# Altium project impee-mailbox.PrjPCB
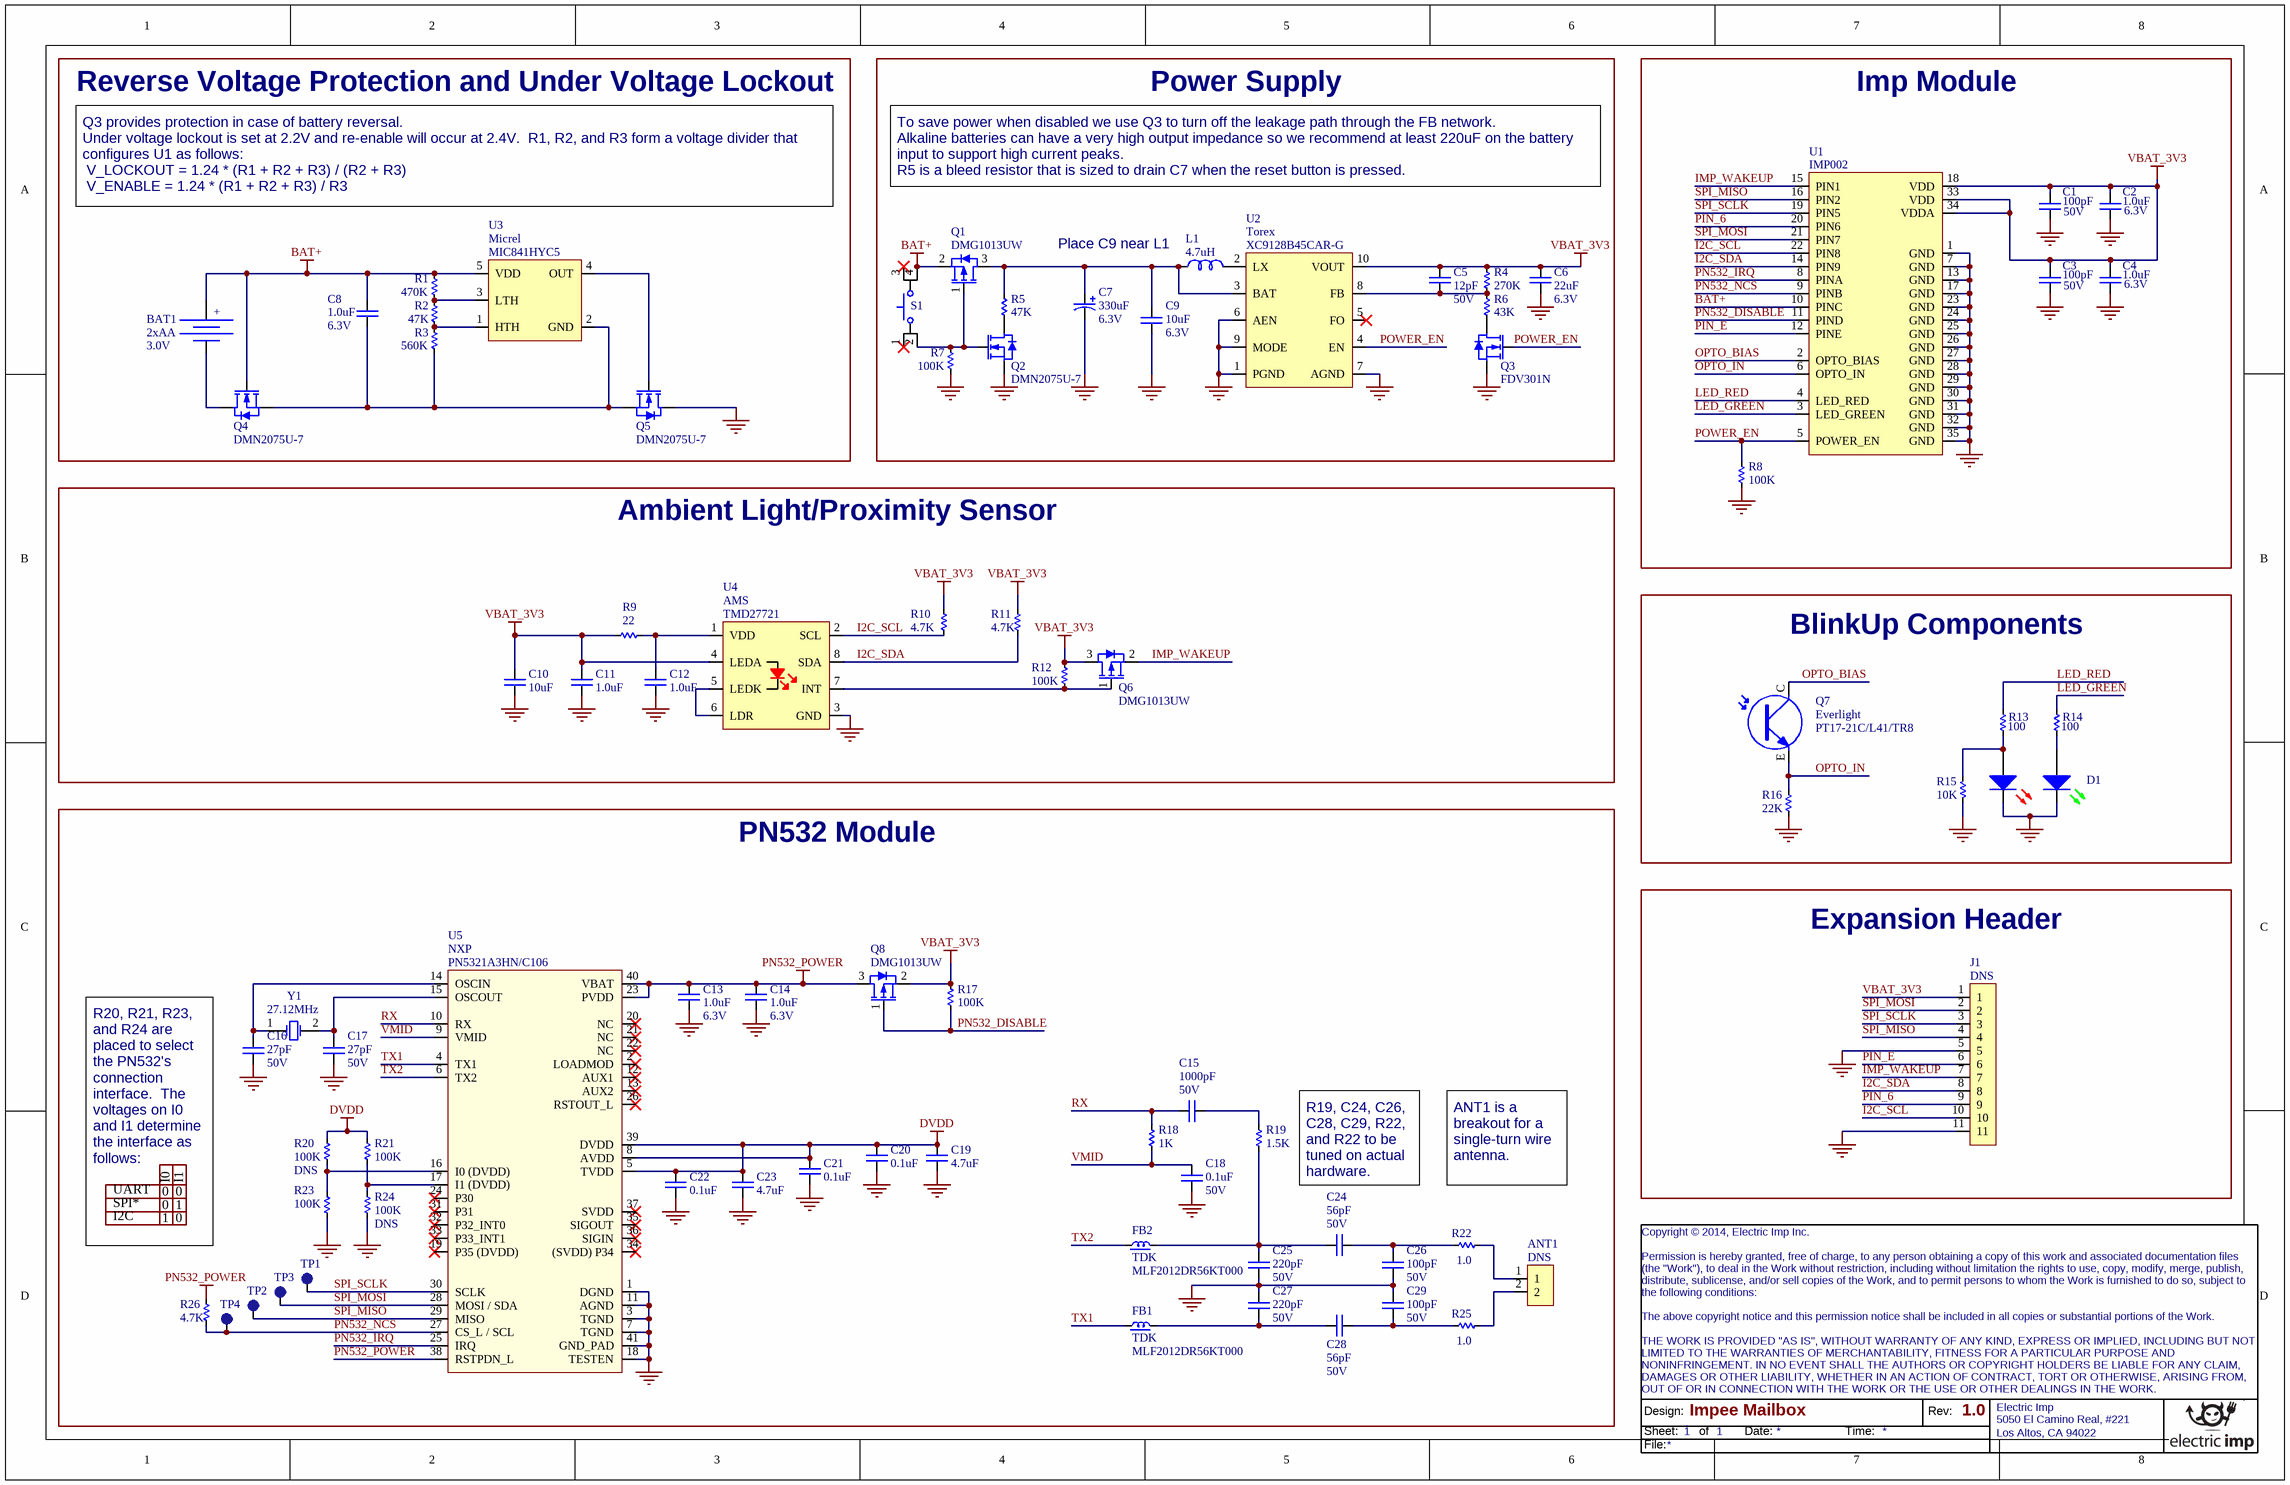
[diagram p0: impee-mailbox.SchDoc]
1 sheet, 81 parts. Net scope: global (net labels, ports and power ports of the same name join across sheets).
Board file: impee-mailbox.PcbDoc

## Sheet impee-mailbox.SchDoc: Impee Mailbox
size Tabloid; Revision: 1.0; SheetNumber: 1; SheetTotal: 1; PageSetup: Record=PageOptions¦CenterHorizontal=True¦CenterVertical=True¦PrintScale=0.90¦XCorrection=1.00¦YCorrection=1.00¦PrintKind=0¦BorderSize=5000000¦LeftOffset=0¦BottomOffset=0¦Orientation=2¦PaperLength=1000¦PaperWidth=1000¦Scale=100¦PaperSource=276¦PrintQuality=-3¦MediaType=1¦DitherType=10¦PrintScaleMode=1¦PaperKind=Tabloid¦PaperIndex=3

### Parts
ANT1  BOMOPTION: DNS  [HDR254P1X2-N]  (hidden comment: Header)  (no BOM)
BAT1  Voltage: 3.0V  Configuration: 2xAA  [12BH321P-GR]  (hidden comment: BATTERY)
C1  value 100pF  Voltage: 50V  [CAPC1005X07N]  (hidden comment: Ceramic Capacitor)
C2  value 1.0uF  Voltage: 6.3V  [CAPC1005X07N]  (hidden comment: Ceramic Capacitor)
C3  value 100pF  Voltage: 50V  [CAPC1005X07N]  (hidden comment: Ceramic Capacitor)
C4  value 1.0uF  Voltage: 6.3V  [CAPC1005X07N]  (hidden comment: Ceramic Capacitor)
C5  value 12pF  Voltage: 50V  [CAPC1005X07N]  (hidden comment: Ceramic Capacitor)
C6  value 22uF  Voltage: 6.3V  [CAPC2012X14N]  (hidden comment: Ceramic Capacitor)
C7  value 330uF  Voltage: 6.3V  [CAPAE8983X55N]  (hidden comment: Polarized Capacitor)
C8  value 1.0uF  Voltage: 6.3V  [CAPC1005X07N]  (hidden comment: Ceramic Capacitor)
C9  value 10uF  Voltage: 6.3V  [CAPC2012X14N]  (hidden comment: Ceramic Capacitor)
C10  value 10uF  [CAPC2012X14N]  (hidden comment: Ceramic Capacitor)
C11  value 1.0uF  [CAPC1005X07N]  (hidden comment: Ceramic Capacitor)
C12  value 1.0uF  [CAPC1005X07N]  (hidden comment: Ceramic Capacitor)
C13  value 1.0uF  Voltage: 6.3V  [CAPC1005X07N]  (hidden comment: Ceramic Capacitor)
C14  value 1.0uF  Voltage: 6.3V  [CAPC1005X07N]  (hidden comment: Ceramic Capacitor)
C15  value 1000pF  Voltage: 50V  [CAPC1005X07N]  (hidden comment: Ceramic Capacitor)
C16  value 27pF  Voltage: 50V  [CAPC1005X07N]  (hidden comment: Ceramic Capacitor)
C17  value 27pF  Voltage: 50V  [CAPC1005X07N]  (hidden comment: Ceramic Capacitor)
C18  value 0.1uF  Voltage: 50V  [CAPC2012X14N]  (hidden comment: Ceramic Capacitor)
C19  value 4.7uF  [CAPC1608X10N]  (hidden comment: Ceramic Capacitor)
C20  value 0.1uF  [CAPC1005X07N]  (hidden comment: Ceramic Capacitor)
C21  value 0.1uF  [CAPC1005X07N]  (hidden comment: Ceramic Capacitor)
C22  value 0.1uF  [CAPC1005X07N]  (hidden comment: Ceramic Capacitor)
C23  value 4.7uF  [CAPC1608X10N]  (hidden comment: Ceramic Capacitor)
C24  value 56pF  Voltage: 50V  [CAPC1005X07N]  (hidden comment: Ceramic Capacitor)
C25  value 220pF  Voltage: 50V  [CAPC1005X07N]  (hidden comment: Ceramic Capacitor)
C26  value 100pF  Voltage: 50V  [CAPC1005X07N]  (hidden comment: Ceramic Capacitor)
C27  value 220pF  Voltage: 50V  [CAPC1005X07N]  (hidden comment: Ceramic Capacitor)
C28  value 56pF  Voltage: 50V  [CAPC1005X07N]  (hidden comment: Ceramic Capacitor)
C29  value 100pF  Voltage: 50V  [CAPC1005X07N]  (hidden comment: Ceramic Capacitor)
D1  LED Red and Green  [LED1616X07N-REDGREEN]  (value not drawn)
FB1  Manufacturer: TDK  Manufacturer Part Number: MLF2012DR56KT000  [INDC2012X11N]  (hidden comment: Ferrite Bead)
FB2  Manufacturer: TDK  Manufacturer Part Number: MLF2012DR56KT000  [INDC2012X11N]  (hidden comment: Ferrite Bead)
J1  BOMOPTION: DNS  [HDR254P1X11-N]  (hidden comment: Header)  (no BOM)
L1  value 4.7uH  [INDP6060X28N]  (hidden comment: Inductor)
Q1  Manufacturer Part Number: DMG1013UW  [SOT65P210X110-3N]  (hidden comment: PFET)
Q2  Manufacturer Part Number: DMN2075U-7  [SOT95P300X130-3N]  (hidden comment: N-Channel MOSFET)
Q3  Manufacturer Part Number: FDV301N  [SOT95P300X130-3N]  (hidden comment: N-Channel MOSFET)
Q4  Manufacturer Part Number: DMN2075U-7  [SOT95P300X130-3N]  (hidden comment: N-Channel MOSFET)
Q5  Manufacturer Part Number: DMN2075U-7  [SOT95P300X130-3N]  (hidden comment: N-Channel MOSFET)
Q6  Manufacturer Part Number: DMG1013UW  [SOT65P210X110-3N]  (hidden comment: PFET)
Q7  Manufacturer: Everlight  Manufacturer Part Number: PT17-21C/L41/TR8  [PHOTOTRANS2012X13]  (hidden comment: PHOTOTRANSISTOR)
Q8  Manufacturer Part Number: DMG1013UW  [SOT65P210X110-3N]  (hidden comment: PFET)
R1  value 470K  [RESC1005X04N]  (hidden comment: Resistor)
R2  value 47K  [RESC1005X04N]  (hidden comment: Resistor)
R3  value 560K  [RESC1005X04N]  (hidden comment: Resistor)
R4  value 270K  [RESC1005X04N]  (hidden comment: Resistor)
R5  value 47K  [RESC1005X04N]  (hidden comment: Resistor)
R6  value 43K  [RESC1005X04N]  (hidden comment: Resistor)
R7  value 100K  [RESC1005X04N]  (hidden comment: Resistor)
R8  value 100K  [RESC1005X04N]  (hidden comment: Resistor)
R9  value 22  [RESC1005X04N]  (hidden comment: Resistor)
R10  value 4.7K  [RESC1005X04N]  (hidden comment: Resistor)
R11  value 4.7K  [RESC1005X04N]  (hidden comment: Resistor)
R12  value 100K  [RESC1005X04N]  (hidden comment: Resistor)
R13  value 100  [RESC1005X04N]  (hidden comment: Resistor)
R14  value 100  [RESC1005X04N]  (hidden comment: Resistor)
R15  value 10K  [RESC1005X04N]  (hidden comment: Resistor)
R16  value 22K  [RESC1005X04N]  (hidden comment: Resistor)
R17  value 100K  [RESC1005X04N]  (hidden comment: Resistor)
R18  value 1K  [RESC1005X04N]  (hidden comment: Resistor)
R19  value 1.5K  [RESC1005X04N]  (hidden comment: Resistor)
R20  value 100K  BOMOPTION: DNS  [RESC1005X04N]  (hidden comment: Resistor)  (no BOM)
R21  value 100K  [RESC1005X04N]  (hidden comment: Resistor)
R22  value 1.0  [RESC2012X07N]  (hidden comment: Resistor)
R23  value 100K  [RESC1005X04N]  (hidden comment: Resistor)
R24  value 100K  BOMOPTION: DNS  [RESC1005X04N]  (hidden comment: Resistor)  (no BOM)
R25  value 1.0  [RESC2012X07N]  (hidden comment: Resistor)
R26  value 4.7K  [RESC1005X04N]  (hidden comment: Resistor)
S1  Push Button  [BTN600X600X430-4N]  (value not drawn)
TP1  Testpoint  [TP254P1X1-TH]  (value not drawn)  (no BOM)
TP2  Testpoint  [TP254P1X1-TH]  (value not drawn)  (no BOM)
TP3  Testpoint  [TP254P1X1-TH]  (value not drawn)  (no BOM)
TP4  Testpoint  [TP254P1X1-TH]  (value not drawn)  (no BOM)
U1  Manufacturer Part Number: IMP002  [IMP_MODULE]  (hidden comment: imp module)
U2  Manufacturer: Torex  Manufacturer Part Number: XC9128B45CAR-G  [MSOP50P490X116-10N]  (hidden comment: XC9128)
U3  Manufacturer: Micrel  Manufacturer Part Number: MIC841HYC5  [SOT65P200X125-5N]  (hidden comment: MIC841)
U4  Manufacturer: AMS  Manufacturer Part Number: TMD27721  [SON97P240X155-8N]  (hidden comment: TMD2772)
U5  Manufacturer: NXP  Manufacturer Part Number: PN5321A3HN/C106  [QFN50P600X600X100_HS-41N]  (hidden comment: PN532)
Y1  Frequency: 27.12MHz  [XTAL5032X135]  (hidden comment: XTAL)

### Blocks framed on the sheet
Reverse Voltage Protection and Under Voltage Lockout: BAT1 C8 Q4 Q5 R1-R3 U3
Power Supply: C5-C7 C9 L1 Q1-Q3 R4-R7 S1 U2
Imp Module: C1-C4 R8 U1
Ambient Light/Proximity Sensor: C10-C12 Q6 R9-R12 U4
BlinkUp Components: D1 Q7 R13-R16
PN532 Module: ANT1 C13-C29 FB1 FB2 Q8 R17-R26 TP1-TP4 U5 Y1
Expansion Header: J1

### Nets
BAT+: BAT1.+ C8.2 Q1.2(S) Q4.1(G) R1.1 S1.4 U1.10(PINC) U3.5(VDD)
DVDD: C19.2 C20.2 C21.2 C22.2 C23.2 R20.1 R21.1 U5.5(TVDD) U5.8(AVDD) U5.39(DVDD)
GND: C1.1 C2.1 C3.1 C4.1 C6.1 C7.2 C9.1 C10.1 C11.1 C12.1 C13.1 C14.1 C16.1 C17.1 C18.1 C19.1 C20.1 C21.1 C22.1 C23.1 C25.1 C26.1 C27.2 C29.2 D1.KG D1.KR J1.5 J1.11 Q2.2(S) Q3.2(S) Q5.3(D) R7.2 R8.2 R15.1 R16.2 R23.2 R24.2 U1.1(GND) U1.7(GND) U1.13(GND) U1.17(GND) U1.23(GND) U1.24(GND) U1.25(GND) U1.26(GND) U1.27(GND) U1.28(GND) U1.29(GND) U1.30(GND) U1.31(GND) U1.32(GND) U1.35(GND) U2.1(PGND) U2.6(AEN) U2.7(AGND) U2.9(MODE) U4.3(GND) U5.1(DGND) U5.3(TGND) U5.7(TGND) U5.11(AGND) U5.18(TESTEN) U5.41(GND_PAD)
PN532_POWER: C13.2 C14.2 Q8.3(D) R26.1 U5.23(PVDD) U5.38(RSTPDN_L) U5.40(VBAT)
VBAT_3V3: C1.2 C2.2 C3.2 C4.2 C5.2 C6.2 C10.2 C11.2 J1.1 Q6.3(D) Q8.2(S) R4.1 R9.2 R10.1 R11.1 R12.1 R17.1 U1.18(VDD) U1.33(VDD) U1.34(VDDA) U2.10(VOUT) U4.4(LEDA)
I2C_SCL: J1.10 R10.2 U1.22(PIN8) U4.2(SCL)
I2C_SDA: J1.8 R11.2 U1.14(PIN9) U4.8(SDA)
IMP_WAKEUP: J1.7 Q6.2(S) U1.15(PIN1)
LED_GREEN: R14.1 U1.3(LED_GREEN)
LED_RED: R13.1 U1.4(LED_RED)
OPTO_BIAS: Q7.C U1.2(OPTO_BIAS)
OPTO_IN: Q7.E R16.1 U1.6(OPTO_IN)
PIN_6: J1.9 U1.20(PIN6)
PIN_E: J1.6 U1.12(PINE)
PN532_DISABLE: Q8.1(G) R17.2 U1.11(PIND)
PN532_IRQ: U1.8(PINA) U5.25(IRQ)
PN532_NCS: R26.2 TP4.1 U1.9(PINB) U5.27(CS_L_/_SCL)
POWER_EN: Q3.1(G) R8.1 U1.5(POWER_EN) U2.4(EN)
RX: C15.1 R18.1 U5.10(RX)
SPI_MISO: J1.4 TP2.1 U1.16(PIN2) U5.29(MISO)
SPI_MOSI: J1.2 TP3.1 U1.21(PIN7) U5.28(MOSI_/_SDA)
SPI_SCLK: J1.3 TP1.1 U1.19(PIN5) U5.30(SCLK)
TX1: FB1.1 U5.4(TX1)
TX2: FB2.1 U5.6(TX2)
VMID: C18.2 R18.2 U5.9(VMID)
NetANT1_1: ANT1.1 R22.2
NetANT1_2: ANT1.2 R25.2
NetBAT1_-: BAT1.- Q4.3(D)
NetC5_1: C5.1 R4.2 R6.1 U2.8(FB)
NetC7_1: C7.1 C9.2 L1.1 Q1.3(D) R5.1 U2.3(BAT)
NetC8_1: C8.1 Q4.2(S) Q5.2(S) R3.2 U3.2(GND)
NetC12_2: C12.2 R9.1 U4.1(VDD)
NetC15_2: C15.2 R19.1
NetC16_2: C16.2 U5.14(OSCIN) Y1.1(OSC1)
NetC17_2: C17.2 U5.15(OSCOUT) Y1.2(OSC2)
NetC24_1: C24.1 C25.2 FB2.2 R19.2
NetC24_2: C24.2 C26.2 R22.1
NetC27_1: C27.1 C28.1 FB1.2
NetC28_2: C28.2 C29.1 R25.1
NetD1_AG: D1.AG R14.2
NetD1_AR: D1.AR R13.2 R15.2
NetL1_2: L1.2 U2.2(LX)
NetQ1_1: Q1.1(G) Q2.1(G) R7.1 S1.2
NetQ2_3: Q2.3(D) R5.2
NetQ3_3: Q3.3(D) R6.2
NetQ5_1: Q5.1(G) U3.4(OUT)
NetQ6_1: Q6.1(G) R12.2 U4.7(INT)
NetR1_2: R1.2 R2.1 U3.3(LTH)
NetR2_2: R2.2 R3.1 U3.1(HTH)
NetR20_2: R20.2 R23.1 U5.16(I0_(DVDD))
NetR21_2: R21.2 R24.1 U5.17(I1_(DVDD))
NetU4_5: U4.5(LEDK) U4.6(LDR)

Not connected (* = marked no-connect by the designer): S1 1* 3*; U2 5(FO)*; U5 2(LOADMOD)* 12(AUX1)* 13(AUX2)* 19(P35_(DVDD))* 20(NC)* 21(NC)* 22(NC)* 24(P30)* 26(RSTOUT_L)* 31(P31)* 32(P32_INT0)* 33(P33_INT1)* 34((SVDD)_P34)* 35(SIGOUT)* 36(SIGIN)* 37(SVDD)*

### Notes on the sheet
- Q3 provides protection in case of battery reversal.
  Under voltage lockout is set at 2.2V and re-enable will occur at 2.4V.  R1, R2, and R3 form a voltage divider that configures U1 as follows:
  V_LOCKOUT = 1.24 * (R1 + R2 + R3) / (R2 + R3)
  V_ENABLE = 1.24 * (R1 + R2 + R3) / R3
- To save power when disabled we use Q3 to turn off the leakage path through the FB network.
  Alkaline batteries can have a very high output impedance so we recommend at least 220uF on the battery input to support high current peaks.
  R5 is a bleed resistor that is sized to drain C7 when the reset button is pressed.
- (near L1) Place C9 near L1
- R20, R21, R23, and R24 are placed to select the PN532's connection interface.  The voltages on I0 and I1 determine the interface as follows:
- UART
- SPI*
- I2C
- 0
- 1
- I0
- I1
- R19, C24, C26, C28, C29, R22, and R22 to be tuned on actual hardware.
- ANT1 is a breakout for a single-turn wire antenna.

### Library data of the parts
ANT1 = HDR00002: HDR, 1x2 Pin, 2.54mm Pitch, Gold Flash, Vertical, TH; Manufacturer: FCI; Manufacturer Part Number: 68000-402HLF; Gender: Male; Connector Type: Unshrouded; Number of Columns: 2
BAT1 = BAT00006: 2xAA Series Battery Clip with Through-Hole PCB Mount; Manufacturer: Eagle Plastic Devices
C1 C3 C26 C29 = CAPC00043: CAP,C0G,100pF,5%,50V,0402; Manufacturer: Yageo; Manufacturer Part Number: CC0402JRNPO9BN101
C2 C4 C8 C11-C14 = CAPC00005: CAP,X5R,1.0uF,10%,6.3V, 0402,#; Manufacturer: Murata; Manufacturer Part Number: GRM155R60J105KE19D
C5 = CAPC00041: CAP,C0G,12pF,5%,50V,0402#; Manufacturer: Yageo; Manufacturer Part Number: CC0402JRNPO9BN120
C6 = CAPC00039: CAP,X5R,22uF,10%,6.3V,0805,#; Manufacturer: TDK; Manufacturer Part Number: C2012X5R0J226K/1.25
C7 = CAPC00106: CAP,Alum,330uF,20%,6.3V,SMD; Manufacturer: Nichicon; Manufacturer Part Number: UWX0J331MCL1GB
C9 C10 = CAPC00036: CAP,X5R,10uF,10%,6.3V,0805,#; Manufacturer: Yageo; Manufacturer Part Number: CC0805KKX5R5BB106
C15 = CAPC00092: CAP,X7R,1000pF,10%,50V,0402; Manufacturer: Samsung; Manufacturer Part Number: CL05B102KB5NCNC
C16 C17 = CAPC00044: CAP,C0G,27pF,5%,50V,0402; Manufacturer: Yageo; Manufacturer Part Number: CC0402JRNPO9BN270
C18 = CAPC00023: CAP,X7R,0.1uF,10%,50V,0805; Manufacturer: AVX; Manufacturer Part Number: 08055C104K
C19 C23 = CAPC00033: CAP,X5R,4.7uF,10%,6.3V,0603,#; Manufacturer: Taiyo Yuden; Manufacturer Part Number: JMK107BJ475KA-T
C20-C22 = CAPC00002: CAP,X5R,0.1uF,10%,6.3V, 0402,#; Manufacturer: TDK; Manufacturer Part Number: C1005X5R0J104K
C24 C28 = CAPC00045: CAP,C0G,56pF,5%,50V,0402; Manufacturer: Yageo; Manufacturer Part Number: CC0402JRNPO9BN560
C25 C27 = CAPC00110: CAP,C0G,220pF,25%,50V,0402; Manufacturer: Samsung; Manufacturer Part Number: CL05C221JB5NNNC; Tolerance: 5%
D1 = LED00012: LED, Red and Green, 2/2V, 631/571nm, 25/35mcd, SMT; Manufacturer: Liteon; Manufacturer Part Number: LTST-C195KGJRKT; Color: Red/Green; Millicandela Rating (min): 25mcd, 35mcd; Voltage - Forward (Vf) Typ: 2V, 2V; Current - Test: 20mA; Wavelength - Dominant: 631nm, 571nm; Wavelength - Peak: 639nm, 574nm; Viewing Angle: 130°; Lens Type: Clear
FB1 FB2 = FB00008: FERR BD, 25 Ohm @ 25Mhz, 150mA, 550 mOhm, 0805
J1 = HDR00036: HDR, 1x11 Pin, 2.54mm Pitch, Gold Flash, Vertical, TH; Manufacturer: TE Connectivity; Manufacturer Part Number: 4-644456-1; Gender: Male; Connector Type: Unshrouded; Number of Columns: 11
L1 = IND00007: IND, 4.7uH, 20%, 2.7A Isat, 403 mOhm, 6028; Manufacturer: Taiyo Yuden; Manufacturer Part Number: NR6028T4R7M
Q1 Q6 Q8 = PFET00009: PFET, 20V, 820mA, 1V, SOT323; Manufacturer: Diodes Inc; Current - Continuous Drain (Id) @ 25° C: DMP3098L; Rds On (Max) @ Id, Vgs: 750 mOhm @ 430mA, 4.5V; Vgs(th) (Max) @ Id: 1V @ 250µA; Power - Max: 310mW
Q2 Q4 Q5 = NFET00004: NFET, 20V, 4.2A, SOT23; Manufacturer: Diodes Incorporated; Rds On (Max) @ Id, Vgs: 45 mOhm @ 3.1A, 2.5V; Vgs(th) (Max) @ Id: 1.0V @ 250uA; Power - Max: 800mW
Q3 = NFET00003: NFET, 25V, 220mA, SOT23; Manufacturer: Fairchild; Rds On (Max) @ Id, Vgs: 5 ohm @ 200mA, 2.7V; Vgs(th) (Max) @ Id: 1.06V @ 250uA; Power - Max: 350mW
Q7 = PHOTO00002: Phototrans, Clear, Top View, 940nm, 0.4V, 1mA, 0805
R1 = RES00009: RES,470K,5%,0.063W,0402; Manufacturer: Yageo; Manufacturer Part Number: RC0402JR-07470KL
R2 R5 = RES00008: RES,47K,5%,0.063W,0402; Manufacturer: Yageo; Manufacturer Part Number: RC0402JR-0747KL
R3 = RES00054: RES,560K,1%,0.063W,0402; Manufacturer: Yageo; Manufacturer Part Number: RC0402FR-07560KL
R4 = RES00015: RES,270K,5%,0.063W,0402; Manufacturer: Yageo; Manufacturer Part Number: RC0402JR-07270KL
R6 = RES00041: RES,43K,1%,0.063W,0402; Manufacturer: Yageo; Manufacturer Part Number: RC0402FR-0743KL
R7 R8 R12 R17 R20 R21 R23 R24 = RES00001: RES,100K,5%,0.063W,0402,#; Manufacturer: Samsung; Manufacturer Part Number: RC1005J104CS
R9 = RES00060: RES,22 Ohm,5%,0.063W,0402; Manufacturer: Yageo; Manufacturer Part Number: RC0402JR-0722RL
R10 R11 R26 = RES00005: RES,4.7K,5%,0.063W,0402,#; Manufacturer: Yageo; Manufacturer Part Number: RC0402JR-074K7L
R13 R14 = RES00024: RES,100,1%,0.063W,0402,#; Manufacturer: Yageo; Manufacturer Part Number: RC0402FR-07100RL
R15 = RES00006: RES,10k,5%,0.063W,0402,#; Manufacturer: Stackpole; Manufacturer Part Number: RMCF0402JT10K0
R16 = RES00007: RES,22K,5%,0.063W,0402; Manufacturer: Yageo; Manufacturer Part Number: RC0402JR-0722KL
R18 = RES00003: RES,1K,5%,0.063W,0402,#; Manufacturer: Yageo; Manufacturer Part Number: RC0402JR-071KL
R19 = RES00100: RES,1.5K Ohm,1%,0.063W,0402; Manufacturer: Rohm; Manufacturer Part Number: MCR01MRTF1501
R22 R25 = RES00018: RES,1 Ohm,1%,0.25W,0805; Manufacturer: ROHM; Manufacturer Part Number: MCR10ERTFL1R00; Power: 0.125
S1 = BTN00001: SPST- NO Momentary Button, 160g Force, SMD; Manufacturer: TE Connectivity; Manufacturer Part Number: FSM4JSMA
TP1-TP4 = ELEC00022
U1 = MOD00002: Module, Electric Imp Solder Down with Antenna
U2 = IC00026: IC, DC/DC boost,Adjustable, 6 VIN, 500mA, MSOP10
U3 = IC00032: IC, Comparator with Reference and Programmable Hysteresis, SOT-353
U4 = IC00196: IC, Sensor, ALS and Proximity, I2C
U5 = IC00195: IC, NFC Reader, QFN40
Y1 = XTAL00003: XTAL, 27.12MHz, 30ppm, 18pF, 50 Ohm, 5032; Manufacturer: TXC; Manufacturer Part Number: 7A-27.120MAAJ-T; Operating Mode: Fundamental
